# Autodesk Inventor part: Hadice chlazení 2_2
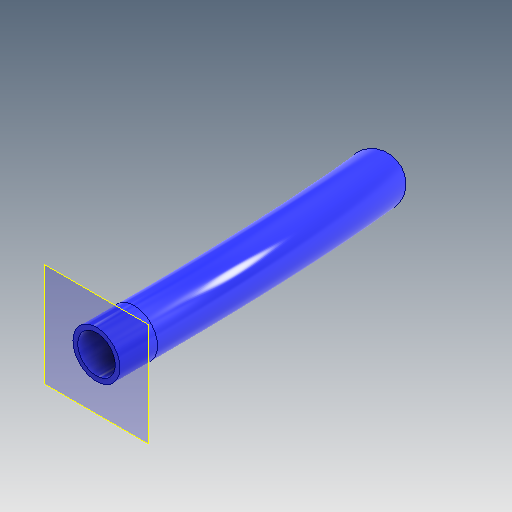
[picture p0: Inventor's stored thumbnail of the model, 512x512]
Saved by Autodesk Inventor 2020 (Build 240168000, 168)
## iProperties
Created: 2025-04
Part Number: Hadice chlazení 2_2
Material: Polyetylen, S nízkou hustotou
Document SubType Name: Modeling
Designer: doma
Density: 0.894 g/cm^3
Appearance: Modrá – nástěnná malba – lesklá
Mass: 1.85473 g
Surface Area: 42.0583 cm^2
Volume: 2.07464 cm^3
Author: doma
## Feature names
1. Tažení1
## Parameters: d1 = 8 mm, d2 = 0, d3 = 0
